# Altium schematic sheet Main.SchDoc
size A; SheetNumber: 1; SheetTotal: 5
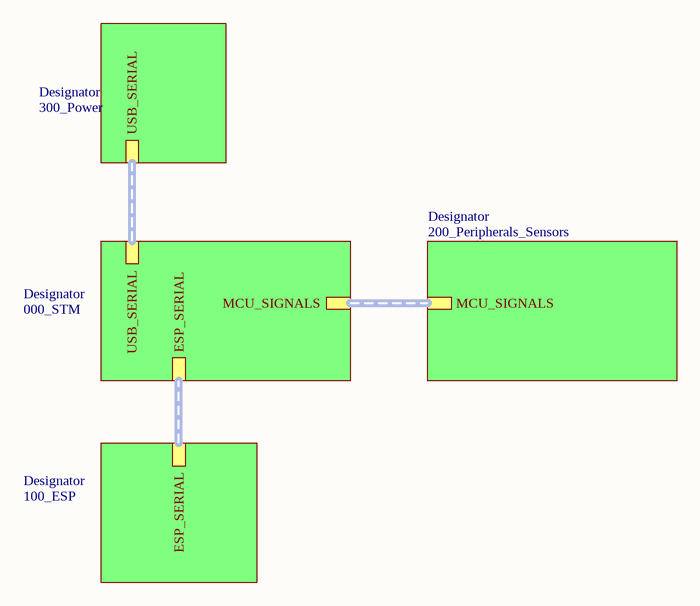
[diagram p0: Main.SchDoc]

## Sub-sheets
Designator = 000_STM: MCU_SIGNALS (harness MCU_SIGNALS), USB_SERIAL (harness USB_SERIAL), ESP_SERIAL (harness ESP_SERIAL)
Designator = 100_ESP: ESP_SERIAL (harness ESP_SERIAL)
Designator = 200_Peripherals_Sensors: MCU_SIGNALS (harness MCU_SIGNALS)
Designator = 300_Power: USB_SERIAL (harness USB_SERIAL)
